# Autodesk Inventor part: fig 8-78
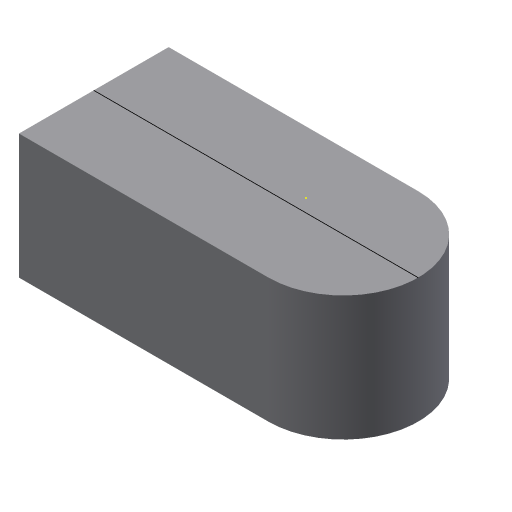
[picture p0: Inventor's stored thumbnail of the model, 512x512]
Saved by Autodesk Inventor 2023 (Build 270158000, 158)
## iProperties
Created: 2011-07
Part Number: fig 8-78
Material: Generic
Document SubType Name: Modeling
Designer: CadCim
Density: 1 g/cm^3
Appearance: Default
Author: CadCim
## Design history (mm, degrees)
sketch "Sketch1"
  geometry: L1 (-16, 5)-(-16, -7); L2 (-16, -7)-(4, -7); L3 (4, 5)-(-16, 5); A1 r 6 centre (4, -1) between (4, -7) and (4, 5); 1 further point
  constraints: 6 end point, 2 point on circle, 2 tangent, 1 centre point, 1 parallel, 1 perpendicular, 1 vertical
extrude "Extrusion1" new body sketch "Sketch1" distance "d0" = 10; taper "d1" = 0 deg
sketch "Sketch2"
  geometry: L1 (-16, -1)-(10, -1); 1 further point
  constraints: 2 end point, 1 horizontal
body "Solid1"
